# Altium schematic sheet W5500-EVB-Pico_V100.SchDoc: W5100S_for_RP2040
size A3; Organization: WIZnet Co., Ltd.; Address1: 5F, Humax Village; Address2: Hwangseaul-ro, Bundang-Gu; Address3: Seongnam-Si, Gyeonggi-Do; Address4: South Korea; Revision: 001; SheetNumber: 1; SheetTotal: 1
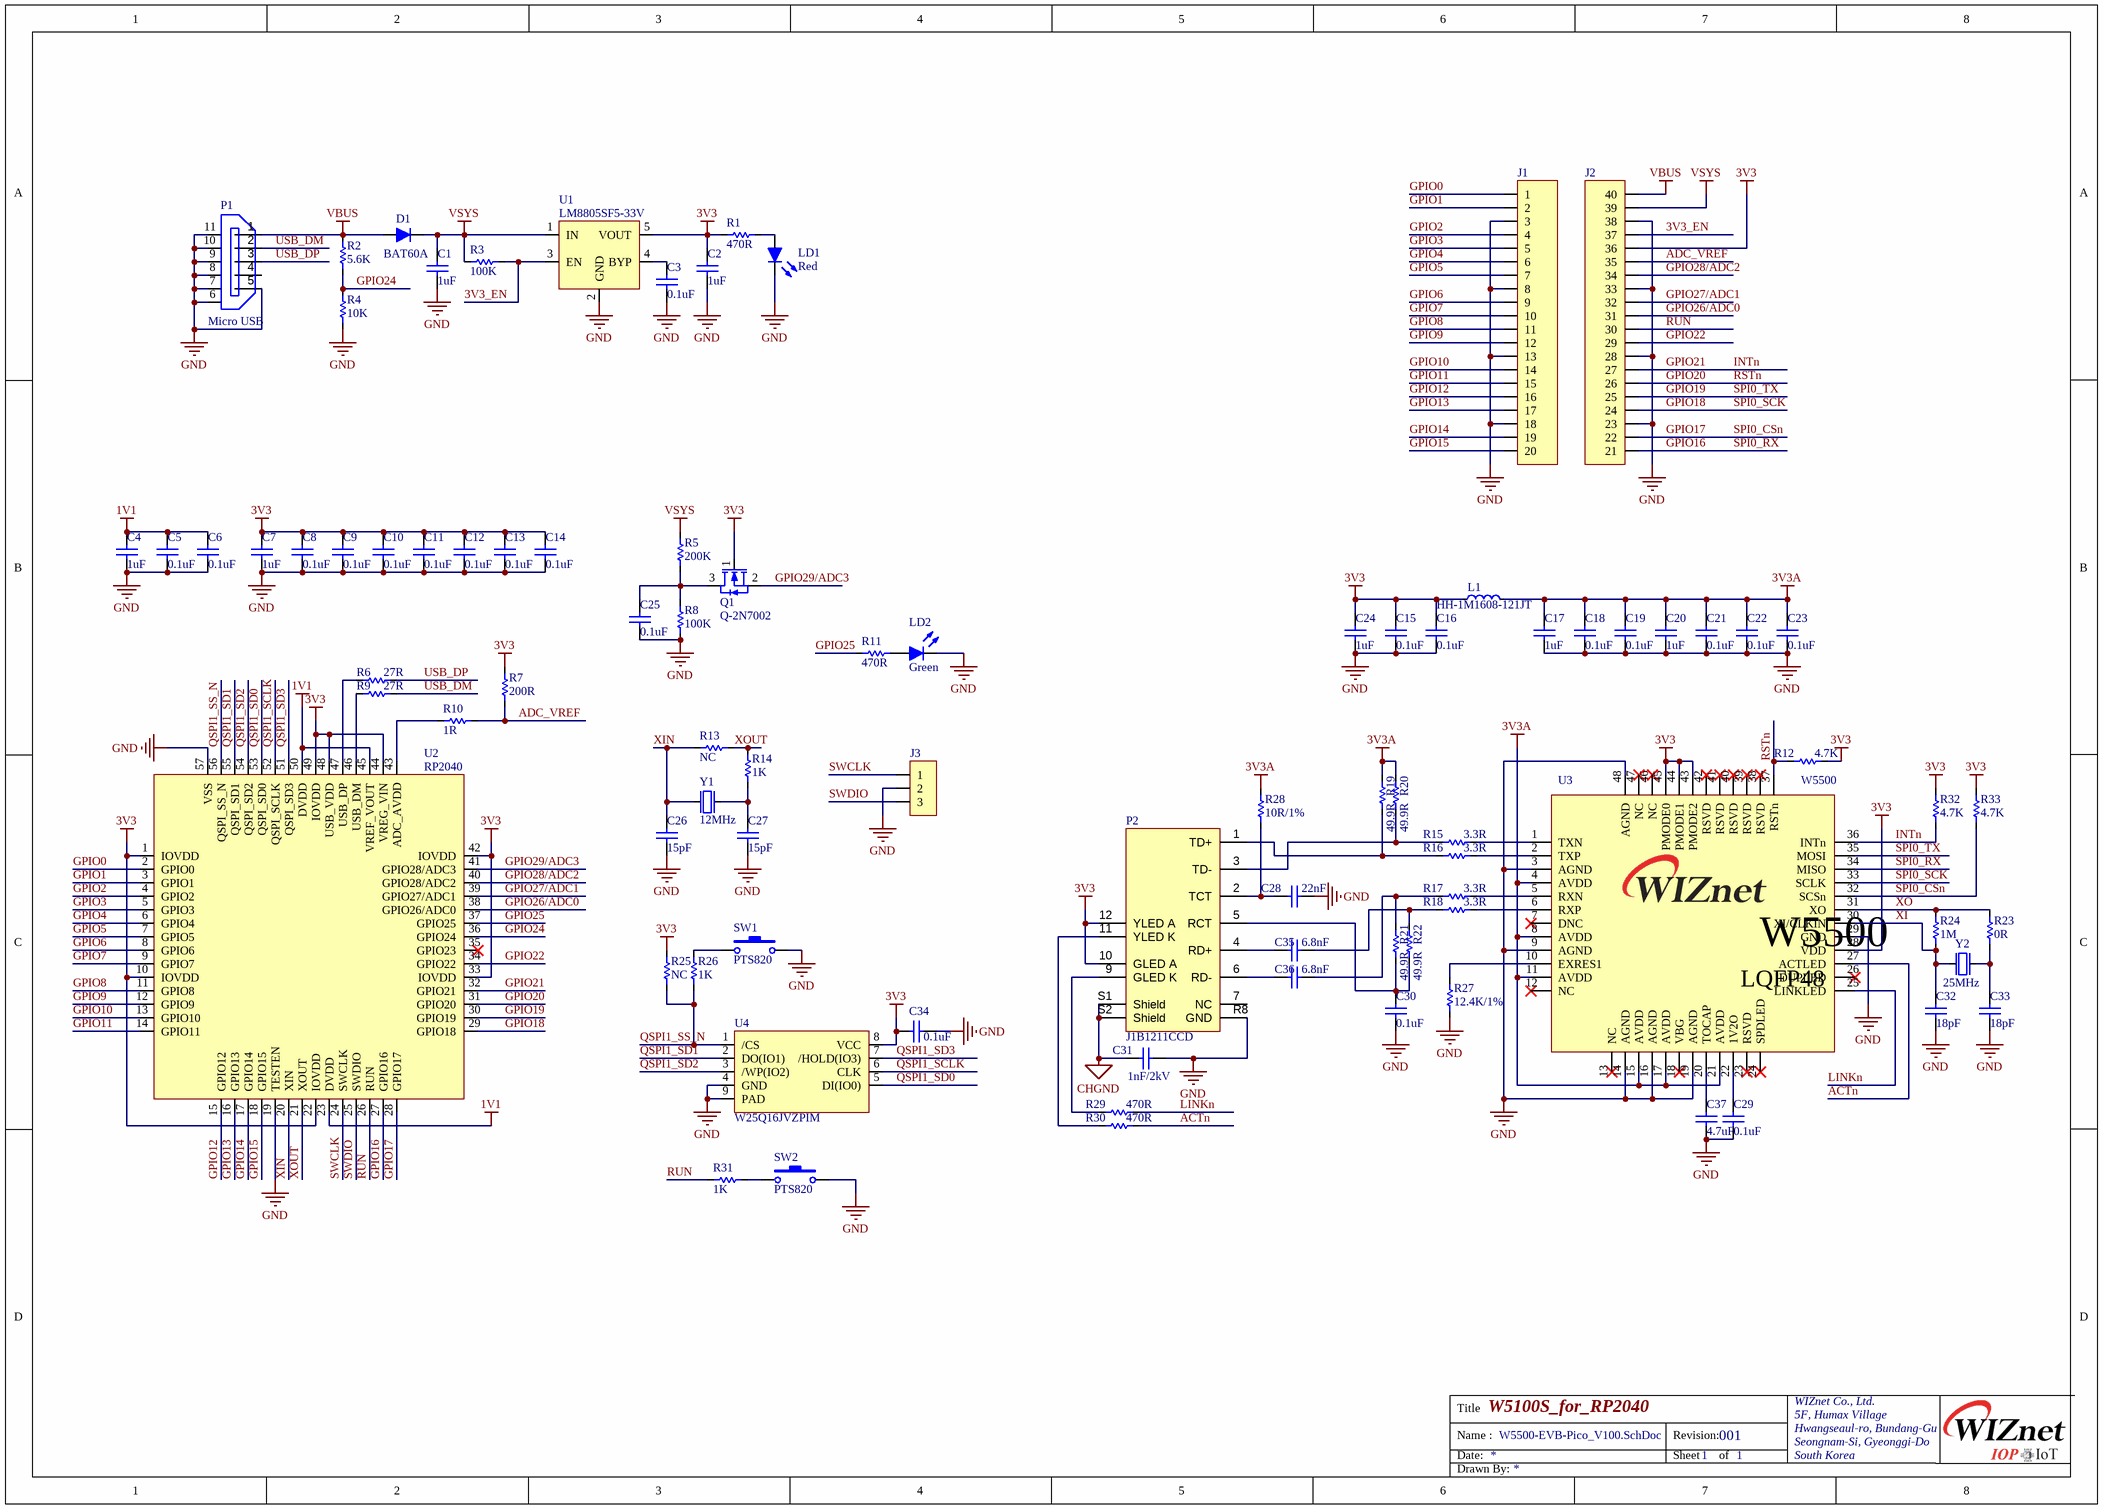
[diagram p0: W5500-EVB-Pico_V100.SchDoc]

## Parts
C1  1uF  [CAP-0402]
C2  1uF  [CAP-0402]
C3  0.1uF  [CAP-0402]
C4  1uF  [CAP-0402]
C5  0.1uF  [CAP-0402]
C6  0.1uF  [CAP-0402]
C7  1uF  [CAP-0402]
C8  0.1uF  [CAP-0402]
C9  0.1uF  [CAP-0402]
C10  0.1uF  [CAP-0402]
C11  0.1uF  [CAP-0402]
C12  0.1uF  [CAP-0402]
C13  0.1uF  [CAP-0402]
C14  0.1uF  [CAP-0402]
C15  0.1uF  [CAP-0402]
C16  0.1uF  [CAP-0402]
C17  1uF  [CAP-0402]
C18  0.1uF  [CAP-0402]
C19  0.1uF  [CAP-0402]
C20  1uF  [CAP-0402]
C21  0.1uF  [CAP-0402]
C22  0.1uF  [CAP-0402]
C23  0.1uF  [CAP-0402]
C24  1uF  [CAP-0402]
C25  0.1uF  [CAP-0402]
C26  15pF  [CAP-0402]
C27  15pF  [CAP-0402]
C28  22nF  [CAP-0402]
C29  0.1uF  [CAP-0402]
C30  0.1uF  [CAP-0402]
C31  1nF/2kV  [CAP-1808]
C32  18pF  [CAP-0402]
C33  18pF  [CAP-0402]
C34  0.1uF  [CAP-0402]
C35  6.8nF  [CAP-0402]
C36  6.8nF  [CAP-0402]
C37  4.7uF  [CAP-0805]
D1  BAT60A  [SOD-323(1-C,2-A)]
J1  2.54mm 1x20 Pin Header DIP  [IDC-1X20]  (value not drawn)
J2  2.54mm 1x20 Pin Header DIP  [IDC-1X20]  (value not drawn)
J3  2.54mm 1x3 Pin Header DIP  [IDC-1X3]  (value not drawn)
L1  HH-1M1608-121JT  [IND-0603]
LD1  Red  [LED-0603-RED]
LD2  Green  [LED-0603-GREEN]
P1  Micro USB  [Micro 5P B DBX 6.4]
P2  J1B1211CCD  [RJ45-J1B1211CCD]
Q1  Q-2N7002  [SOT23-3L]
R1  470R  [RES-0402]
R2  5.6K  [RES-0402]
R3  100K  [RES-0402]
R4  10K  [RES-0402]
R5  200K  [RES-0402]
R6  27R  [RES-0402]
R7  200R  [RES-0402]
R8  100K  [RES-0402]
R9  27R  [RES-0402]
R10  1R  [RES-0402]
R11  470R  [RES-0402]
R12  4.7K  [RES-0402]
R13  NC  [RES-0402]
R14  1K  [RES-0402]
R15  3.3R  [RES-0402]
R16  3.3R  [RES-0402]
R17  3.3R  [RES-0402]
R18  3.3R  [RES-0402]
R19  49.9R  [RES-0402]
R20  49.9R  [RES-0402]
R21  49.9R  [RES-0402]
R22  49.9R  [RES-0402]
R23  0R  [RES-0402]
R24  1M  [RES-0402]
R25  NC  [RES-0402]
R26  1K  [RES-0402]
R27  12.4K/1%  [RES-0402]
R28  10R/1%  [RES-0402]
R29  470R  [RES-0402]
R30  470R  [RES-0402]
R31  1K  [RES-0402]
R32  4.7K  [RES-0402]
R33  4.7K  [RES-0402]
SW1  PTS820  [PTS820]
SW2  PTS820  [PTS820]
U1  LM8805SF5-33V  [SOT-23-5L]
U2  RP2040  [QFN56(0.4/7X7)]
U3  W5500  [W5500-LQFP48]
U4  W25Q16JVZPIM  [WSON8(6X5_1.27)]
Y1  12MHz  [OSC-TZ1067B]
Y2  25MHz  [OSC-82J0626]

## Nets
1V1: C4.2 C5.2 C6.2 U2.23(DVDD) U2.45(VREF_VOUT) U2.50(DVDD)
3V3: C2.2 C7.2 C8.2 C9.2 C10.2 C11.2 C12.2 C13.2 C14.2 C15.2 C16.2 C24.2 C34.2 J2.16(36) L1.1 P2.10(GLED_A) P2.12(YLED_A) Q1.1(G) R1.1 R7.1 R12.2 R25.2 R32.1 R33.1 U1.5(VOUT) U2.1(IOVDD) U2.10(IOVDD) U2.22(IOVDD) U2.33(IOVDD) U2.42(IOVDD) U2.44(VREG_VIN) U2.48(USB_VDD) U2.49(IOVDD) U3.28(VDD) U3.43(PMODE2) U3.44(PMODE1) U3.45(PMODE0) U4.8(VCC)
3V3A: C17.2 C18.2 C19.2 C20.2 C21.2 C22.2 C23.2 L1.2 R19.2 R20.2 R28.1 U3.4(AVDD) U3.8(AVDD) U3.11(AVDD) U3.15(AVDD) U3.17(AVDD) U3.21(AVDD)
CHGND: C31.2 P2.S1(Shield) P2.S2(Shield)
GND: C1.1 C2.1 C3.1 C4.1 C5.1 C6.1 C7.1 C8.1 C9.1 C10.1 C11.1 C12.1 C13.1 C14.1 C15.1 C16.1 C17.1 C18.1 C19.1 C20.1 C21.1 C22.1 C23.1 C24.1 C25.2 C26.2 C27.2 C28.1 C29.1 C30.1 C31.1 C32.1 C33.1 C34.1 C37.1 J1.3 J1.8 J1.13 J1.18 J2.3(23) J2.8(28) J2.13(33) J2.18(38) J3.2 LD1.2(K) LD2.2(K) P1.5 P1.6 P1.7 P1.8 P1.9 P1.10 P1.11 P2.R8(GND) R4.1 R8.1 R27.2 SW1.2 SW2.2 U1.2(GND) U2.19(TESTEN) U2.57(VSS) U3.3(AGND) U3.9(AGND) U3.14(AGND) U3.16(AGND) U3.19(AGND) U3.29(GND) U3.48(AGND) U4.4(GND) U4.9(PAD) Y1.2 Y1.4 Y2.2(GND) Y2.4(GND)
VBUS: D1.2(A) J2.20(40) P1.1 R2.2
VSYS: C1.2 D1.1(K) J2.19(39) R3.1 R5.2 U1.1(IN)
3V3_EN: J2.17(37) R3.2 U1.3(EN)
ACTn: R30.2 U3.27(ACTLED)
ADC_VREF: J2.15(35) R7.2 R10.2
GPIO0: J1.1 U2.2(GPIO0)
GPIO1: J1.2 U2.3(GPIO1)
GPIO2: J1.4 U2.4(GPIO2)
GPIO3: J1.5 U2.5(GPIO3)
GPIO4: J1.6 U2.6(GPIO4)
GPIO5: J1.7 U2.7(GPIO5)
GPIO6: J1.9 U2.8(GPIO6)
GPIO7: J1.10 U2.9(GPIO7)
GPIO8: J1.11 U2.11(GPIO8)
GPIO9: J1.12 U2.12(GPIO9)
GPIO10: J1.14 U2.13(GPIO10)
GPIO11: J1.15 U2.14(GPIO11)
GPIO12: J1.16 U2.15(GPIO12)
GPIO13: J1.17 U2.16(GPIO13)
GPIO14: J1.19 U2.17(GPIO14)
GPIO15: J1.20 U2.18(GPIO15)
GPIO16: J2.1(21) U2.27(GPIO16) U3.34(MISO)  [also labelled SPI0_RX]
GPIO17: J2.2(22) R33.2 U2.28(GPIO17) U3.32(SCSn)  [also labelled SPI0_CSn]
GPIO18: J2.4(24) U2.29(GPIO18) U3.33(SCLK)  [also labelled SPI0_SCK]
GPIO19: J2.5(25) U2.30(GPIO19) U3.35(MOSI)  [also labelled SPI0_TX]
GPIO20: J2.6(26) R12.1 U2.31(GPIO20) U3.37(RSTn)  [also labelled RSTn]
GPIO21: J2.7(27) R32.2 U2.32(GPIO21) U3.36(INTn)  [also labelled INTn]
GPIO22: J2.9(29) U2.34(GPIO22)
GPIO24: R2.1 R4.2 U2.36(GPIO24)
GPIO25: R11.2 U2.37(GPIO25)
GPIO26/ADC0: J2.11(31) U2.38(GPIO26/ADC0)
GPIO27/ADC1: J2.12(32) U2.39(GPIO27/ADC1)
GPIO28/ADC2: J2.14(34) U2.40(GPIO28/ADC2)
GPIO29/ADC3: Q1.2(S) U2.41(GPIO28/ADC3)
LINKn: R29.2 U3.25(LINKLED)
QSPI1_SCLK: U2.52(QSPI_SCLK) U4.6(CLK)
QSPI1_SD0: U2.53(QSPI_SD0) U4.5(DI(IO0))
QSPI1_SD1: U2.55(QSPI_SD1) U4.2(DO(IO1))
QSPI1_SD2: U2.54(QSPI_SD2) U4.3(/WP(IO2))
QSPI1_SD3: U2.51(QSPI_SD3) U4.7(/HOLD(IO3))
QSPI1_SS_N: R25.1 R26.1 U2.56(QSPI_SS_N) U4.1(/CS)
RUN: J2.10(30) R31.2 U2.26(RUN)
SWCLK: J3.1 U2.24(SWCLK)
SWDIO: J3.3 U2.25(SWDIO)
USB_DM: P1.2 R9.1
USB_DP: P1.3 R6.1
XI: C32.2 R24.1 U3.30(XI/CLKIN) Y2.1(inp)
XIN: C26.1 R13.2 U2.20(XIN) Y1.1(inp)
XO: R23.2 R24.2 U3.31(XO)
XOUT: R13.1 R14.2 U2.21(XOUT)
NetC3_2: C3.2 U1.4(BYP)
NetC25_1: C25.1 Q1.3(D) R5.1 R8.2
NetC27_1: C27.1 R14.1 Y1.3(out)
NetC28_2: C28.2 P2.2(TCT) R28.2
NetC29_2: C29.2 U3.22(1V2O)
NetC30_2: C30.2 P2.5(RCT) R21.1 R22.1
NetC33_2: C33.2 R23.1 Y2.3(out)
NetC35_1: C35.1 R18.1 R22.2
NetC35_2: C35.2 P2.4(RD+)
NetC36_1: C36.1 R17.1 R21.2
NetC36_2: C36.2 P2.6(RD-)
NetC37_2: C37.2 U3.20(TOCAP)
NetLD1_1: LD1.1(A) R1.2
NetLD2_1: LD2.1(A) R11.1
NetP2_1: P2.1(TD+) R16.1 R19.1
NetP2_3: P2.3(TD-) R15.1 R20.1
NetP2_9: P2.9(GLED_K) R29.1
NetP2_11: P2.11(YLED_K) R30.1
NetR6_2: R6.2 U2.47(USB_DP)
NetR9_2: R9.2 U2.46(USB_DM)
NetR10_1: R10.1 U2.43(ADC_AVDD)
NetR15_2: R15.2 U3.1(TXN)
NetR16_2: R16.2 U3.2(TXP)
NetR17_2: R17.2 U3.5(RXN)
NetR18_2: R18.2 U3.6(RXP)
NetR26_2: R26.2 SW1.1
NetR27_1: R27.1 U3.10(EXRES1)
NetR31_1: R31.1 SW2.1

Not connected (* = marked no-connect by the designer): P1 4; P2 7(NC); U2 35(GPIO23)*; U3 7(DNC)* 12(NC)* 13(NC)* 18(VBG)* 23(RSVD)* 24(SPDLED)* 26(DUPLED)* 38(RSVD)* 39(RSVD)* 40(RSVD)* 41(RSVD)* 42(RSVD)* 46(NC)* 47(NC)*

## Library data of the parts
C1-C30 C32-C36 = CAP-0402: Ceramic CAP 0402(1005)
C31 = CAP-1808: Ceramic CAP 1808(4520)
C37 = CAP-0805: Ceramic CAP 0805(2012)
D1 = DIODE-BAT60A: Silicon Schottky Diode
L1 = IND-0603: Inductor 0603(1608)
LD1 LD2 = LED-0603
P1 = Micro USB 5P DBX6.4: Micro USB B Connector SMD
Q1 = Q-2N7002: N-Channel 60-V (D-S) MOSFET
R1-R33 = RES-0402
SW1 SW2 = ITS-1107(SMD): TACT Switch (SMD)
U1 = LM8805SF5-33V: 600mA CMOS LDO Regulator
U2 = RP2040: Raspverry Pi, Dual ARM Cortex-M0+ @ 133MHz
U3 = W5500: WIZnet Hardwired TCP/IP Chip
U4 = W25Q16JVZPIM: 3V 16M-BIT / SERIAL FLASH MEMORY WITH / DUAL/QUAD SPI, QPI & DTR
Y1 = OSC-TZ1067B-12MHz: X-tal 12MHz,3.2x2.5 SMD, CL=20pF
Y2 = OSC-82J0626-25MHz: X-tal 25MHz,3.2x2.5 SMD, CL=18pF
